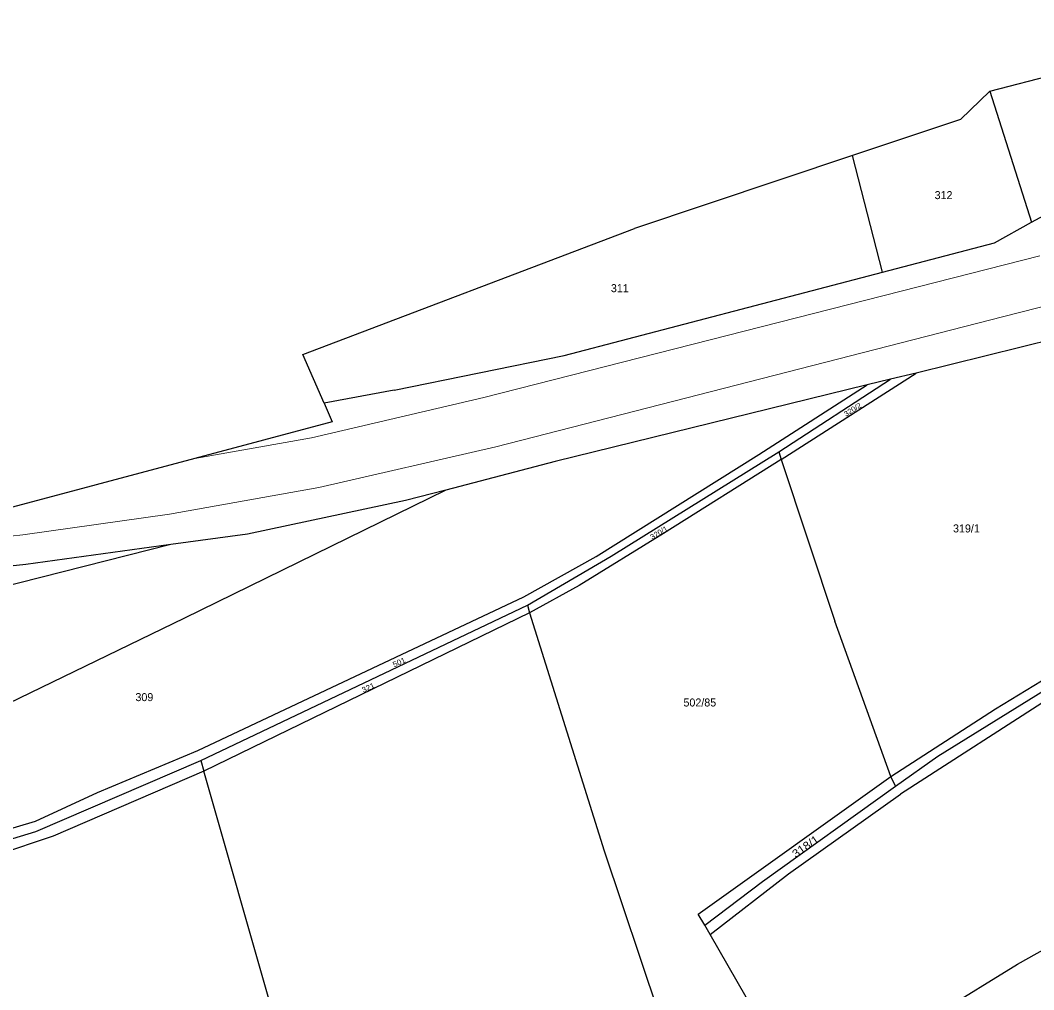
# Model space of a CAD drawing. Extents: x -701211 to -698780, y -1014269 to -1012378.
# Drawn here: x -699614.3 to -699399.1, y -1012872.2 to -1012666.4 of the extents above; entities that cross this region are included whole.
import ezdxf
from ezdxf.enums import TextEntityAlignment as Align

# ---------------------------------------------------------------- set-up
doc = ezdxf.new("R2010")
doc.units = 0
doc.header["$LTSCALE"] = 0.68
doc.layers.add('1', color=7, linetype='Continuous', lineweight=25)
doc.layers.add('4', color=7, linetype='Continuous', lineweight=13)
doc.layers.add('2', color=7, linetype='Continuous')

msp = doc.modelspace()

# ---------------------------------------------------------------- linework, layer by layer
at = {"layer": '1'}
for p, q in [((-699408.49, -1012681.5), (-699350.67, -1012666.42)), ((-699414.68, -1012687.46), (-699408.49, -1012681.5)), ((-699408.49, -1012681.5), (-699399.58, -1012709.31)), ((-699414.68, -1012687.46), (-699437.65, -1012695.14)), ((-699437.65, -1012695.14), (-699483.89, -1012710.6)), ((-699431.28, -1012719.88), (-699437.65, -1012695.14)), ((-699399.58, -1012709.31), (-699396.07, -1012707.38)), ((-699554.34, -1012737.34), (-699483.89, -1012710.6)), ((-699407.5, -1012713.66), (-699399.58, -1012709.31)), ((-699431.28, -1012719.88), (-699407.5, -1012713.66)), ((-699498.86, -1012737.56), (-699431.28, -1012719.88)), ((-699394.39, -1012734), (-699424.13, -1012741.3)), ((-699549.84, -1012747.7), (-699554.34, -1012737.34)), ((-699534.95, -1012744.95), (-699498.86, -1012737.56)), ((-699453.29, -1012758.01), (-699429.56, -1012742.63)), ((-699452.75, -1012759.65), (-699424.13, -1012741.3)), ((-699429.56, -1012742.63), (-699434.49, -1012743.84)), ((-699424.13, -1012741.3), (-699429.56, -1012742.63)), ((-699534.95, -1012744.95), (-699549.84, -1012747.7)), ((-699434.49, -1012743.84), (-699500.73, -1012760.11)), ((-699457.51, -1012758.57), (-699434.49, -1012743.84)), ((-699549.84, -1012747.7), (-699548.13, -1012751.68)), ((-699548.13, -1012751.68), (-699577.27, -1012759.44)), ((-699488.84, -1012780.19), (-699453.29, -1012758.01)), ((-699453.29, -1012758.01), (-699452.75, -1012759.65)), ((-699577.27, -1012759.44), (-699652.51, -1012779.48)), ((-699500.73, -1012760.11), (-699523.96, -1012766.14)), ((-699492.07, -1012780.21), (-699457.51, -1012758.57)), ((-699452.75, -1012759.65), (-699477.76, -1012775.38)), ((-699452.75, -1012759.65), (-699441.36, -1012793.95)), ((-699523.96, -1012766.14), (-699579.58, -1012793.42)), ((-699523.96, -1012766.14), (-699532.53, -1012768.36)), ((-699532.53, -1012768.36), (-699566.08, -1012775.51)), ((-699566.08, -1012775.51), (-699582.37, -1012777.73)), ((-699477.76, -1012775.38), (-699495.63, -1012786.42)), ((-699582.37, -1012777.73), (-699697.77, -1012806.84)), ((-699582.37, -1012777.73), (-699613.16, -1012781.91)), ((-699507.42, -1012788.83), (-699492.07, -1012780.21)), ((-699506.62, -1012790.61), (-699488.84, -1012780.19)), ((-699613.16, -1012781.91), (-699689.06, -1012790.54)), ((-699495.63, -1012786.42), (-699506.18, -1012792.22)), ((-699576.64, -1012821.43), (-699507.42, -1012788.83)), ((-699576, -1012823.57), (-699506.62, -1012790.61)), ((-699506.18, -1012792.22), (-699575.33, -1012825.79)), ((-699506.62, -1012790.61), (-699506.18, -1012792.22)), ((-699506.18, -1012792.22), (-699490.38, -1012842.72)), ((-699579.58, -1012793.42), (-699639.24, -1012822.29)), ((-699429.46, -1012826.96), (-699441.36, -1012793.95)), ((-699419.52, -1012822.62), (-699371.98, -1012793.19)), ((-699407.28, -1012812.58), (-699374.6, -1012792.64)), ((-699378.11, -1012798.88), (-699427.4, -1012830.73)), ((-699429.46, -1012826.96), (-699407.28, -1012812.58)), ((-699597.92, -1012830.32), (-699576.64, -1012821.43)), ((-699611.06, -1012838.62), (-699576, -1012823.57)), ((-699576, -1012823.57), (-699575.33, -1012825.79)), ((-699428.47, -1012829.02), (-699419.52, -1012822.62)), ((-699575.33, -1012825.79), (-699607.36, -1012839.61)), ((-699560.16, -1012878.94), (-699575.33, -1012825.79)), ((-699470.4, -1012856.14), (-699429.46, -1012826.96)), ((-699456.75, -1012849.23), (-699428.47, -1012829.02)), ((-699428.47, -1012829.02), (-699429.46, -1012826.96)), ((-699611.11, -1012836.43), (-699597.92, -1012830.32)), ((-699451.19, -1012847.61), (-699427.4, -1012830.73)), ((-699402.57, -1012866.78), (-699345.45, -1012834.51)), ((-699681.49, -1012857.08), (-699611.11, -1012836.43)), ((-699664.08, -1012854.54), (-699611.06, -1012838.62)), ((-699607.36, -1012839.61), (-699630.7, -1012847.42)), ((-699490.38, -1012842.72), (-699465.56, -1012916.61)), ((-699467.88, -1012860.46), (-699451.19, -1012847.61)), ((-699468.96, -1012858.48), (-699456.75, -1012849.23)), ((-699468.96, -1012858.48), (-699470.4, -1012856.14)), ((-699467.88, -1012860.46), (-699468.96, -1012858.48)), ((-699448.1, -1012894.65), (-699467.88, -1012860.46)), ((-699448.1, -1012894.65), (-699402.57, -1012866.78))]:
    msp.add_line(p, q, dxfattribs=at)
at = {"layer": '4'}
for p, q in [((-699405.78, -1012729.37), (-699281.95, -1012697.62)), ((-699515.93, -1012746.49), (-699397.81, -1012716.39)), ((-699513.35, -1012756.97), (-699405.78, -1012729.37)), ((-699552.49, -1012755.09), (-699515.93, -1012746.49)), ((-699552.49, -1012755.09), (-699577.27, -1012759.44)), ((-699550.97, -1012765.57), (-699513.35, -1012756.97)), ((-699582.64, -1012771.26), (-699550.97, -1012765.57)), ((-699613.8, -1012775.68), (-699582.64, -1012771.26)), ((-699649.87, -1012779.33), (-699613.8, -1012775.68))]:
    msp.add_line(p, q, dxfattribs=at)

# ---------------------------------------------------------------- texts
at = {"layer": '2'}
for s, p in [('312', (-699418.289, -1012704.385)), ('311', (-699487.029, -1012724.135)), ('319/1', (-699413.43, -1012775.135)), ('309', (-699587.989, -1012810.945)), ('502/85', (-699470.04, -1012812.085))]:
    msp.add_text(s, height=1.7, dxfattribs=at).set_placement(p, align=Align.CENTER)
for s, height, rotation, width, p in [('320/2', 1.14, 32, 1.05, (-699437.3041, -1012749.5549)), ('320/1', 1.14, 31, 1.05, (-699478.4336, -1012775.6838)), ('501', 1.14, 24, 1.1, (-699533.6658, -1012803.2078)), ('321', 1.14, 25, 1.1, (-699540.2159, -1012808.6008)), ('318/1', 1.7, 35, 1.1, (-699447.1275, -1012842.5034))]:
    msp.add_text(s, height=height, rotation=rotation, dxfattribs=dict(at, width=width)).set_placement(p, align=Align.CENTER)

doc.saveas('drawing.dxf')
